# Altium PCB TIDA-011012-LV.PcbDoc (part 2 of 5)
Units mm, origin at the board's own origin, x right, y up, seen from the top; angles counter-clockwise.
Board outline 250 x 280 mm, 4 copper layers (Top Layer, Layer 1, Layer 2, Bottom Layer), stack 2.208 mm thick; 410 components, 230 nets, 1280 pads, 1868 vias.
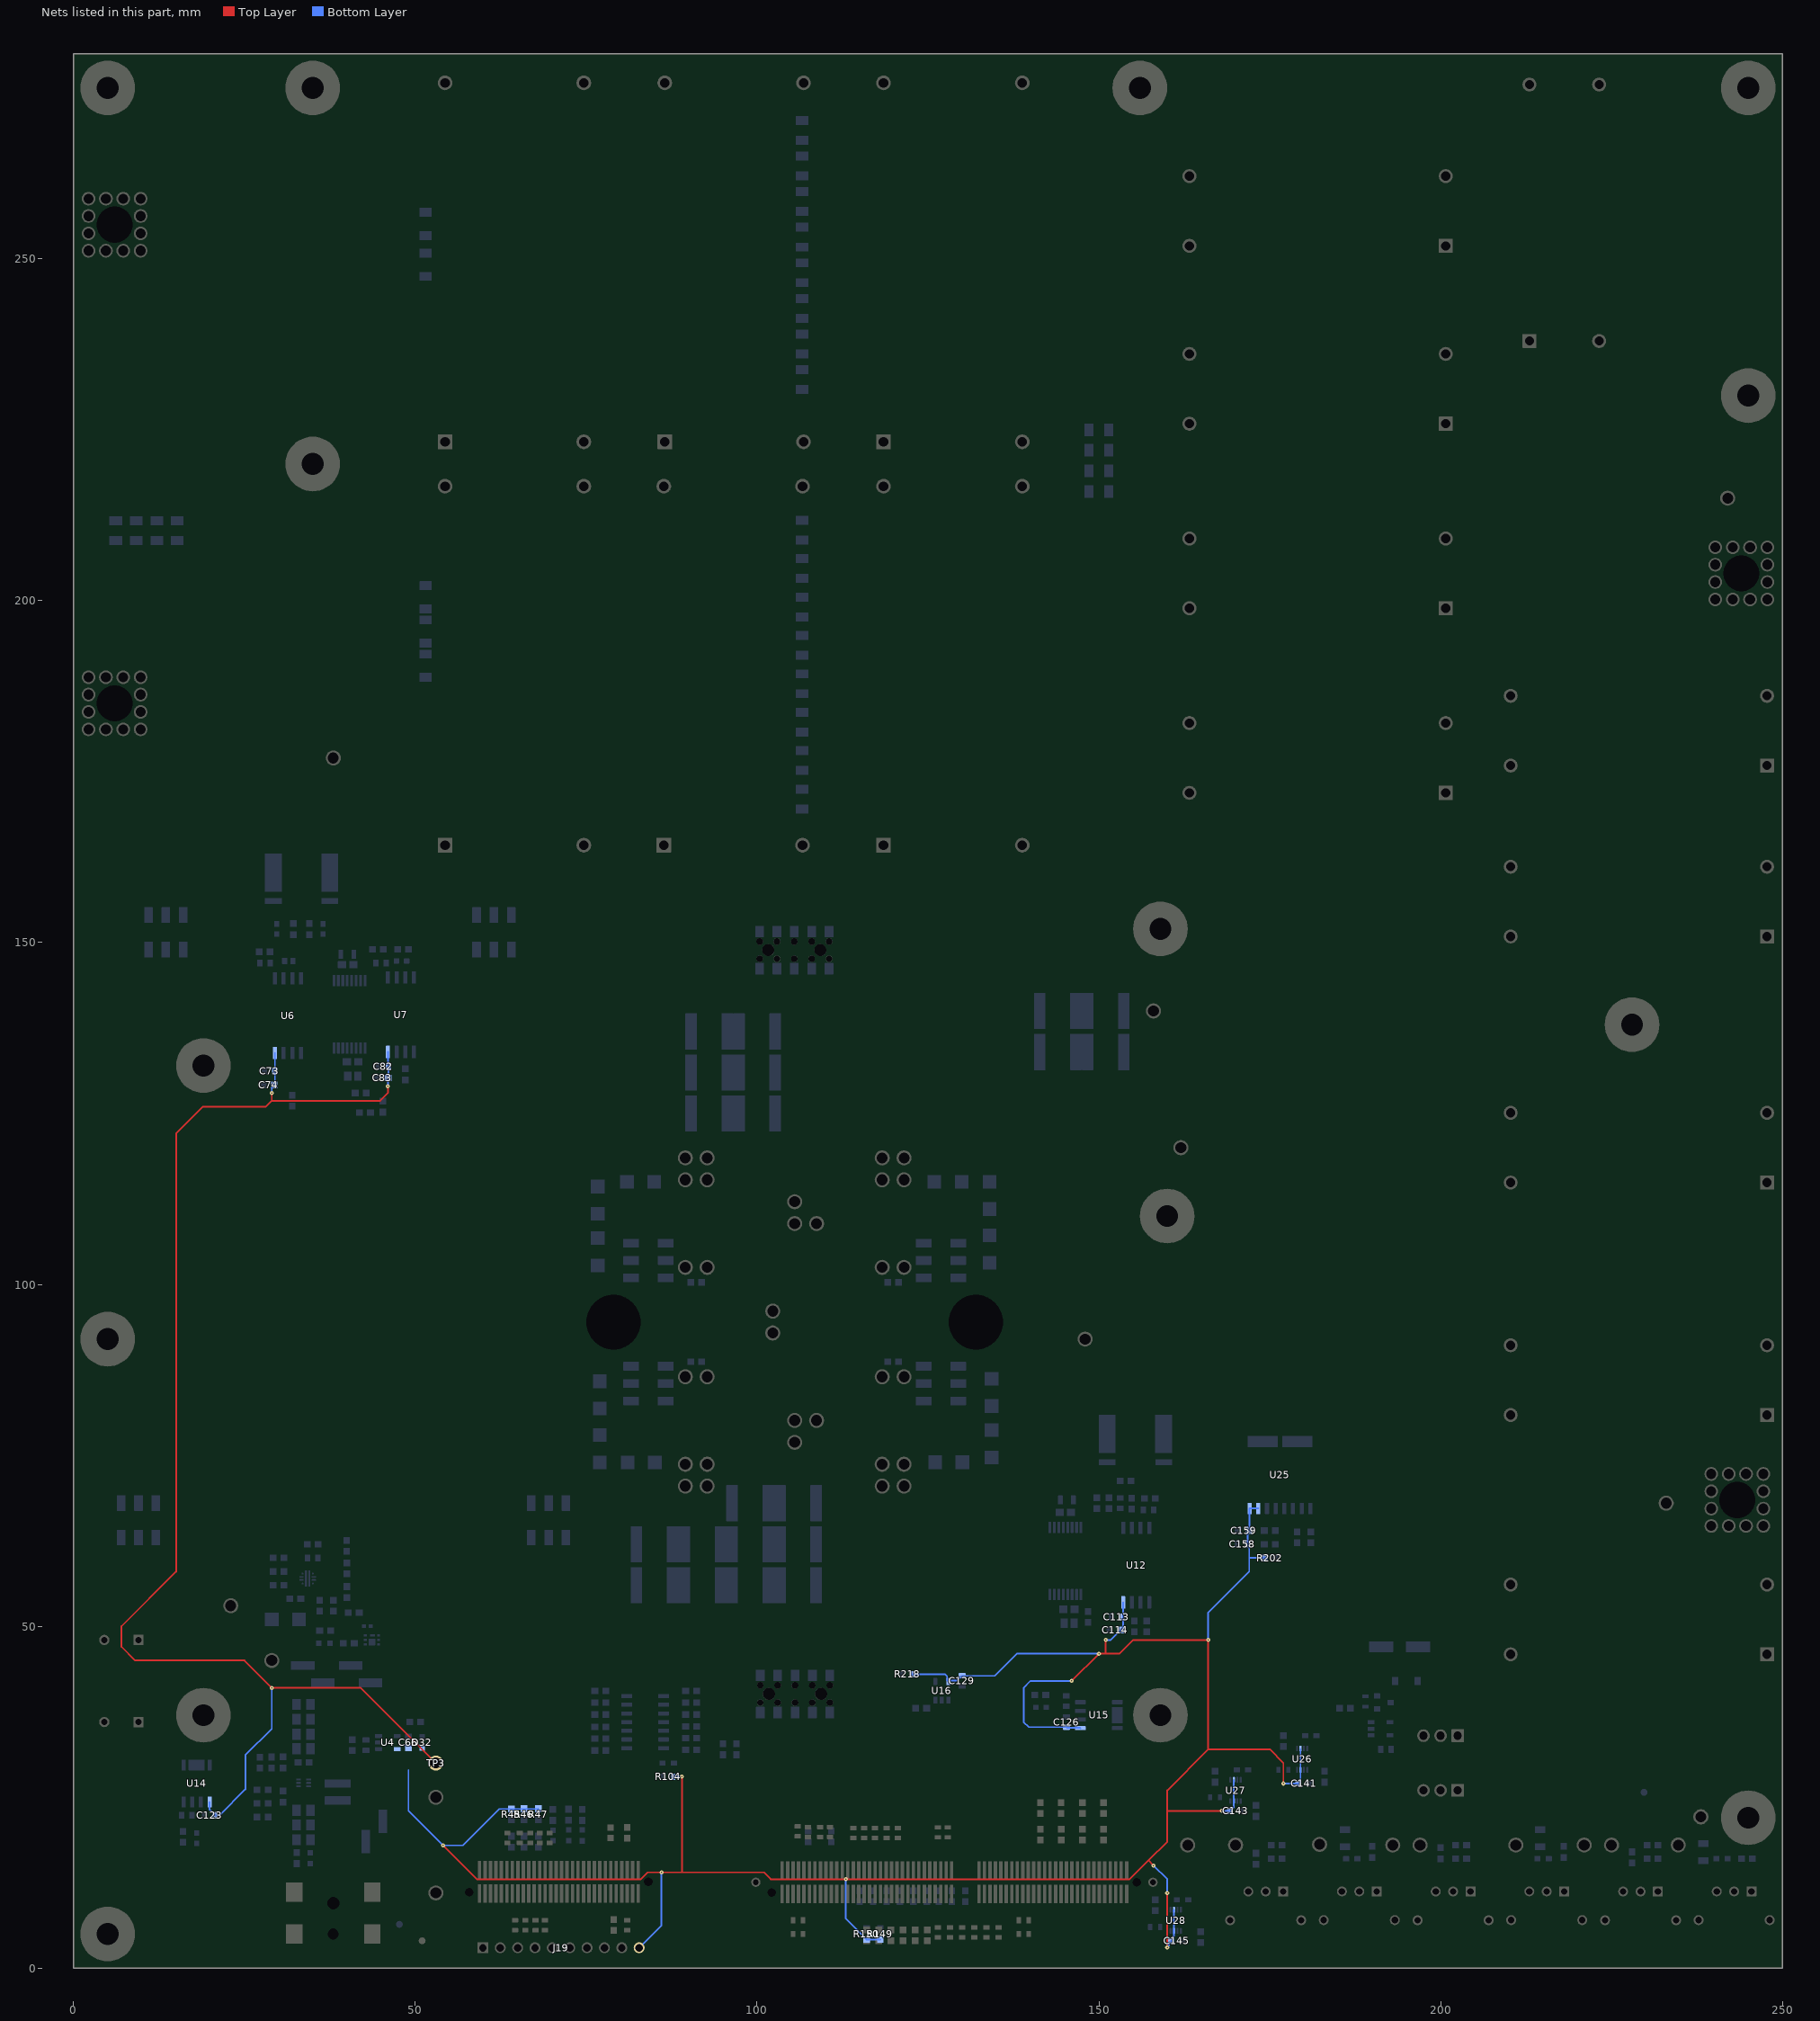
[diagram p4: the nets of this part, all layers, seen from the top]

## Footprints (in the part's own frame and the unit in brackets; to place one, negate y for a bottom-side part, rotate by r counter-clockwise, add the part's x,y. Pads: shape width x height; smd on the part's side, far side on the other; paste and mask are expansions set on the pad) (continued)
controlCARD-120HSEC [mm] "Pads are not numbered according to Samtec datasheet."
  rect 0.5x2.724 smd: 1(-23.357,-1.678) 2(-23.357,1.722) 3(-22.557,-1.678) 4(-22.557,1.722) 5(-21.757,-1.678) 6(-21.757,1.722) 7(-20.957,-1.678) 8(-20.957,1.722) 9(-20.157,-1.678) 10(-20.157,1.722) 11(-19.357,-1.678) 12(-19.357,1.722) 13(-18.557,-1.678) 14(-18.557,1.722) 15(-17.757,-1.678) 16(-17.757,1.722) 17(-16.957,-1.678) 18(-16.957,1.722) 19(-16.157,-1.678) 20(-16.157,1.722) 21(-15.357,-1.678) 22(-15.357,1.722) 23(-14.557,-1.678) 24(-14.557,1.722) 25(-13.757,-1.678) 26(-13.757,1.722) 27(-12.957,-1.678) 28(-12.957,1.722) 29(-12.157,-1.678) 30(-12.157,1.722) 31(-11.357,-1.678) 32(-11.357,1.722) 33(-10.557,-1.678) 34(-10.557,1.722) 35(-9.757,-1.678) 36(-9.757,1.722) 37(-8.957,-1.678) 38(-8.957,1.722) 39(-8.157,-1.678) 40(-8.157,1.722) 41(-7.357,-1.678) 42(-7.357,1.722) 43(-6.557,-1.678) 44(-6.557,1.722) 45(-5.757,-1.678) 46(-5.757,1.722) 47(-4.957,-1.678) 48(-4.957,1.722) 49(-4.157,-1.678) 50(-4.157,1.722) 51(-3.357,-1.678) 52(-3.357,1.722) 53(-2.557,-1.678) 54(-2.557,1.722) 55(-1.757,-1.678) 56(-1.757,1.722) 57(2.243,-1.678) 58(2.243,1.722) 59(3.043,-1.678) 60(3.043,1.722) 61(3.843,-1.678) 62(3.843,1.722) 63(4.643,-1.678) 64(4.643,1.722) 65(5.443,-1.678) 66(5.443,1.722) 67(6.243,-1.678) 68(6.243,1.722) 69(7.043,-1.678) 70(7.043,1.722) 71(7.843,-1.678) 72(7.843,1.722) 73(8.643,-1.678) 74(8.643,1.722) 75(9.443,-1.678) 76(9.443,1.722) 77(10.243,-1.678) 78(10.243,1.722) 79(11.043,-1.678) 80(11.043,1.722) 81(11.843,-1.678) 82(11.843,1.722) 83(12.643,-1.678) 84(12.643,1.722) 85(13.443,-1.678) 86(13.443,1.722) 87(14.243,-1.678) 88(14.243,1.722) 89(15.043,-1.678) 90(15.043,1.722) 91(15.843,-1.678) 92(15.843,1.722) 93(16.643,-1.678) 94(16.643,1.722) 95(17.443,-1.678) 96(17.443,1.722) 97(18.243,-1.678) 98(18.243,1.722) 99(19.043,-1.678) 100(19.043,1.722) 101(19.843,-1.678) 102(19.843,1.722) 103(20.643,-1.678) 104(20.643,1.722) 105(21.443,-1.678) 106(21.443,1.722) 107(22.243,-1.678) 108(22.243,1.722) 109(23.043,-1.678) 110(23.043,1.722) 111(23.843,-1.678) 112(23.843,1.722) 113(24.643,-1.678) 114(24.643,1.722) 115(25.443,-1.678) 116(25.443,1.722) 117(26.243,-1.678) 118(26.243,1.722) 119(27.043,-1.678) 120(27.043,1.722)
  round 0.025 hole 1.27 unplated mask+0.876: 181(-24.857,0.022) 182(28.543,1.522)
  round 1.348 hole 0.84: 185(-27.207,0.022) 186(30.893,0.022)
  silkscreen extent -32.11,-3.86 35.8,3.9, body extent -31.75,-3.47 35.3,3.53, height 12.35
controlCARD-180HSEC-60pinAddon [mm] "Pads are not numbered according to datasheet."
  round 0.025 hole 1.27 unplated mask+0.876: 61(-13.1,0) 62(13.1,1.5)
  rect 0.5x2.724 smd: 121(-11.6,-1.7) 122(-11.6,1.7) 123(-10.8,-1.7) 124(-10.8,1.7) 125(-10,-1.7) 126(-10,1.7) 127(-9.2,-1.7) 128(-9.2,1.7) 129(-8.4,-1.7) 130(-8.4,1.7) 131(-7.6,-1.7) 132(-7.6,1.7) 133(-6.8,-1.7) 134(-6.8,1.7) 135(-6,-1.7) 136(-6,1.7) 137(-5.2,-1.7) 138(-5.2,1.7) 139(-4.4,-1.7) 140(-4.4,1.7) 141(-3.6,-1.7) 142(-3.6,1.7) 143(-2.8,-1.7) 144(-2.8,1.7) 145(-2,-1.7) 146(-2,1.7) 147(-1.2,-1.7) 148(-1.2,1.7) 149(-0.4,-1.7) 150(-0.4,1.7) 151(0.4,-1.7) 152(0.4,1.7) 153(1.2,-1.7) 154(1.2,1.7) 155(2,-1.7) 156(2,1.7) 157(2.8,-1.7) 158(2.8,1.7) 159(3.6,-1.7) 160(3.6,1.7) 161(4.4,-1.7) 162(4.4,1.7) 163(5.2,-1.7) 164(5.2,1.7) 165(6,-1.7) 166(6,1.7) 167(6.8,-1.7) 168(6.8,1.7) 169(7.6,-1.7) 170(7.6,1.7) 171(8.4,-1.7) 172(8.4,1.7) 173(9.2,-1.7) 174(9.2,1.7) 175(10,-1.7) 176(10,1.7) 177(10.8,-1.7) 178(10.8,1.7) 179(11.6,-1.7) 180(11.6,1.7)
  silkscreen extent -14.68,-3.88 14.68,3.88, body extent -14.3,-3.5 14.3,3.5, height 7.95
CUI_PJ-002AH-SMT [mm] "CUI"
  rect 2.8x2.4 smd: 1(-3.05,5.7) 1A(3.05,5.7) 2(-3.05,-5.7) 3(3.05,-5.7)
  round 1 hole 1.6 unplated: MH1(-3.05,0)
  round 1.524 hole 1.8 unplated: MH2(1.45,0)
  silkscreen extent -8.05,-4.5 6.75,5.45, body extent -8.05,-6.3 6.75,6.3, height 11.2
D0014A-MFG [mm]
  rrect17% 1.55x0.6 smd paste-1000 mask+0: 1(-2.7,3.81) 2(-2.7,2.54) 3(-2.7,1.27) 4(-2.7,0) 5(-2.7,-1.27) 6(-2.7,-2.54) 7(-2.7,-3.81) 8(2.7,-3.81) 9(2.7,-2.54) 10(2.7,-1.27) 11(2.7,0) 12(2.7,1.27) 13(2.7,2.54) 14(2.7,3.81)
  silkscreen extent -4.15,-4.38 1.55,4.38, body extent -3,-4.33 3,4.33, height 1.75
DBV0005A_N [mm] "SOT23, 5-Leads, Body 2.9x1.6mm, Pitch 0.95mm, Lead Span 2.8mm, IPC Medium Density"
  rrect17% 1x0.6 smd: 1(-1.375,0.95) 2(-1.375,0) 3(-1.375,-0.95) 4(1.375,-0.95) 5(1.375,0.95)
  silkscreen extent -0.25,-1.55 0.25,1.55, body extent -1.42,-1.46 1.42,1.46, height 1.09
DCU0008A-MFG [mm]
  rrect33% 0.8x0.3 smd paste-1000 mask+0: 1(-1.55,0.75) 2(-1.55,0.25) 3(-1.55,-0.25) 4(-1.55,-0.75) 5(1.55,-0.75) 6(1.55,-0.25) 7(1.55,0.25) 8(1.55,0.75)
  silkscreen extent -2.62,-1.05 0.78,1.05, body extent -1.55,-1 1.55,1, height 0.9
DFQ0007A-MFG [mm]
  rrect17% 1.55x0.6 smd paste+0 mask+0: 1(-2.7,1.905) 2(-2.7,0.635) 3(-2.7,-0.635) 4(-2.7,-1.905) 5(2.7,-1.905) 7(2.7,1.905)
  rrect6% 1.55x2.36 smd paste+0 mask+0: 6(2.7,0)
  silkscreen extent -4.14,-2.5 1.55,2.5, body extent -3.01,-2.45 3.01,2.45, height 1.75
DHA0016A-MFG [mm]
  rrect24% 1.65x0.41 smd paste+0 mask+0: 1(-4.925,2.275) 2(-4.925,1.625) 3(-4.925,0.975) 4(-4.925,0.325) 5(-4.925,-0.325) 6(-4.925,-0.975) 7(-4.925,-1.625) 8(-4.925,-2.275) 9(4.925,-2.275) 10(4.925,-1.625) 11(4.925,-0.975) 12(4.925,-0.325) 13(4.925,0.325) 14(4.925,0.975) 15(4.925,1.625) 16(4.925,2.275)
  silkscreen extent -6.42,-2.98 3.5,2.98, body extent -5.15,-2.93 5.15,2.93, height 2.6
DQK0006C [mm] "WSON"
  rrect12% 0.9x0.86 on Bottom Paste: 0(0,0.325)
  rrect34% 0.7x0.29 on Bottom Paste: 0(0.095,-0.65)
  rrect33% 0.45x0.3 smd: 1(-0.975,0.65) 2(-0.975,0) 3(-0.975,-0.65) 4(0.975,-0.65) 5(0.975,0) 6(0.975,0.65)
  rrect33% 0.75x0.3 smd paste-0.15: 7(0.095,-0.65)
  rrect11% 1x0.95 smd paste-0.5: 8(0,0.325)
  silkscreen extent -1.15,-1.15 1.15,1.15, body extent -1,-1 1,1, height 0.82
DRL0006A-MFG [mm]
  rrect33% 0.67x0.3 smd paste+0 mask+0: 1(-0.74,0.5) 2(-0.74,0) 3(-0.74,-0.5) 4(0.74,-0.5) 5(0.74,0) 6(0.74,0.5)
  silkscreen extent -1.75,-1.05 0.65,1.05, body extent -0.8,-0.8 0.8,0.8, height 0.6
DVG0010A-MFG [mm]
  rrect6% 1.65x4.41 smd paste+0 mask+0: 1(-4.875,2.54) 2(-4.875,-2.54)
  rrect17% 1.65x0.6 smd paste+0 mask+0: 3(4.875,-4.445) 4(4.875,-3.175) 5(4.875,-1.905) 6(4.875,-0.635) 7(4.875,0.635) 8(4.875,1.905) 9(4.875,3.175) 10(4.875,4.445)
  silkscreen extent -6.37,-5.25 3.67,5.25, body extent -5.15,-5.15 5.15,5.15, height 2.65
DWV0008A [mm] "SOIC, 8-Leads, Body 5.95x7.6mm (max), Pitch 1.27mm"
  rrect17% 1.8x0.6 smd: 1(-5.45,1.905) 2(-5.45,0.635) 3(-5.45,-0.635) 4(-5.45,-1.905) 5(5.45,-1.905) 6(5.45,-0.635) 7(5.45,0.635) 8(5.45,1.905)
  silkscreen extent -6.25,-2.95 2.98,2.95, body extent -5.77,-2.92 5.77,2.93, height 2.67
DWV0008A-MFG [mm] "Recommended Land Pattern"
  rrect17% 1.8x0.6 smd paste+0 mask+0: 1(-5.45,1.905) 2(-5.45,0.635) 3(-5.45,-0.635) 4(-5.45,-1.905) 5(5.45,-1.905) 6(5.45,-0.635) 7(5.45,0.635) 8(5.45,1.905)
  silkscreen extent -7.1,-2.98 3.8,2.98, body extent -5.75,-2.93 5.75,2.93, height 2.8
FCC_disclaimer [mm]
Fiducial10-20 [mm]
  round 1 smd mask+0.5: 1(0,0)
  Top Layer keep-out circle w1.178: c0,0 r0.5
FP-0603ZC102KAT2A_0603-MFG [mm]
  rrect13% 0.8x0.75 smd paste+0 mask+0: 1(-0.75,0) 2(0.75,0)
  silkscreen extent -0.87,-0.77 0.87,0.77, body extent -0.8,-0.41 0.8,0.41, height 0.9
FP-06031C101JAT2A_0603-MFG [mm]
  rrect13% 0.8x0.75 smd paste+0 mask+0: 1(-0.75,0) 2(0.75,0)
  silkscreen extent -0.87,-0.77 0.87,0.77, body extent -0.8,-0.41 0.8,0.41, height 0.9
FP-0022111031_HDR3-MFG [mm]
  rrect5% 1.85x1.85 hole 1.2 paste-2539.97 mask+0: 1(2.5,0.3)
  round 1.85 hole 1.2 paste-2539.97 mask+0: 2(0,0.3) 3(-2.5,0.3)
  silkscreen extent -4.1,-3.1 4.7,3.1, body extent -3.5,-2.9 3.5,2.9, height 12.1
FP-74439324047_SMD2-MFG [mm] "Recommended Land Pattern"
  rrect8% 1.2x3.8 smd paste+0 mask+0: 1(-1.225,0) 2(1.225,0)
  silkscreen extent -2.87,-2.25 0.25,2.25, body extent -2.15,-2.15 2.15,2.15, height 3.2
FP-C4AQJBW5550M3MJ_PTH_CAP_57MM5_30MM0-MFG [mm] "Recommended Land Pattern"
  round 2.15 hole 1.4 paste-2539.97 mask+0: 1(-26.25,-10.15) 2(26.25,-10.15) 2(26.25,10.15)
  rrect5% 2.15x2.15 hole 1.4 paste-2539.97 mask+0: 1(-26.25,10.15)
  silkscreen extent -29.15,-15.25 29.15,15.25, body extent -28.75,-15 28.75,15, height 45.3
FP-C4ASMBW4200A3HJ_RADIAL-MFG [mm] "Recommended Land Pattern"
  round 2.05 hole 1.35 paste-2539.97 mask+0: 1(-18.75,-5.1) 2(18.75,-5.1) 2(18.75,5.1)
  rrect5% 2.05x2.05 hole 1.35 paste-2539.97 mask+0: 1(-18.75,5.1)
  silkscreen extent -20.75,-12 20.75,12, body extent -20.75,-12 20.75,12, height 44
FP-C0603C103J3GAC7867_0603-MFG [mm]
  rrect13% 0.75x0.9 smd paste+0 mask+0: 1(-0.6,0) 2(0.6,0)
  silkscreen extent -0.87,-0.82 0.87,0.82, body extent -0.8,-0.4 0.8,0.4, height 0.87
FP-C0603C153K5RACTU_0603-IPC_A [mil]
  rrect9% 47.5x41.66 smd paste+0 mask+0: 1(-32.51,0) 2(32.51,0)
  body extent -31,-16 31,16, height 34
FP-C2220X103KHRAC7800_2220-MFG [mm] "Recommended Land Pattern"
  rrect6% 1.7x5.3 smd paste+0 mask+0: 1(-2.65,0) 2(2.65,0)
  silkscreen extent -1.43,-2.7 1.43,2.7, body extent -2.95,-2.5 2.95,2.5, height 2.2
FP-CHV1206-FX-1504ELF_1206-MFG [mm]
  rrect8% 1.3x1.8 smd paste+0 mask+0: 1(-1.7,0) 2(1.7,0)
  silkscreen extent -0.67,-0.85 0.67,0.85, body extent -1.55,-0.8 1.55,0.8, height 0.65
FP-CL10B104KA8VPJC_0603-MFG [mm]
  rrect13% 0.79x1 smd paste+0 mask+0: 1(-0.755,0) 2(0.755,0)
  silkscreen extent -0.9,-0.87 0.9,0.87, body extent -0.8,-0.4 0.8,0.4, height 0.9
FP-CL10B105KA8VPJC_0603-MFG [mm]
  rrect13% 0.79x1 smd paste+0 mask+0: 1(-0.755,0) 2(0.755,0)
  silkscreen extent -0.9,-0.87 0.9,0.87, body extent -0.8,-0.4 0.8,0.4, height 0.9
FP-CRCW060310K0JNEBC_0603-MFG [mm]
  rrect20% 0.5x0.9 smd paste+0 mask+0: 1(-0.75,0) 2(0.75,0)
  silkscreen extent -0.13,-0.45 0.13,0.45, body extent -0.77,-0.4 0.77,0.4, height 0.5
FP-DMN3042L-13_SOT23-MFG [mm]
  rrect13% 0.9x0.8 smd paste+0 mask+0: 1(-1,0.95) 2(-1,-0.95) 3(1,0)
  silkscreen extent -0.7,-1.5 0.7,1.5, body extent -1.2,-1.45 1.2,1.45, height 1.1
FP-ERJ-H3G0R00V_0603-IPC_B [mm]
  rrect10% 0.957x0.962 smd paste+0 mask+0: 1(-0.751,0) 2(0.751,0)
  silkscreen extent -1.23,-0.88 1.23,0.88, body extent -0.8,-0.4 0.8,0.4, height 0.55
FP-ERJ-H3G0R00V_0603-MFG [mm]
  rrect15% 0.65x0.9 smd paste+0 mask+0: 1(-0.725,0) 2(0.725,0)
  silkscreen extent 0,-0.48 0,0.48, body extent -0.8,-0.4 0.8,0.4, height 0.55
FP-G4H22MT33GB4_SiCPAK-G+_MODIFIED-MFG [mm] "Recommended Land Pattern Modified"
  round 2.2 hole 1.6 paste-2539.97 mask+0: AC1(20.8,12.8) AC1(20.8,16) AC1(24,12.8) AC1(24,16) AC2(-24,12.8) AC2(-24,16) AC2(-20.8,12.8) AC2(-20.8,16) DC1+(20.8,-16) DC1+(20.8,-12.8) DC1+(24,-16) DC1+(24,-12.8) DC1-(14.4,0) DC1-(14.4,3.2) DC1-(17.6,0) DC2+(-24,-16) DC2+(-24,-12.8) DC2+(-20.8,-16) DC2+(-20.8,-12.8) DC2-(-17.6,0) DC2-(-14.4,0) DC2-(-14.4,3.2) G1(8,-12.8) G2(8,12.8) G3(-8,-12.8) G4(-8,12.8) KS1(8,-16) KS2(8,16) KS3(-8,-16) KS4(-8,16) T1(-1.6,-3.2) T2(1.6,-3.2)
  round 4.6 hole 8 unplated paste-2539.97 mask+0: ""(0,26.5) ""(0,-26.5)
  silkscreen extent -28.45,-24.1 29.12,24.1, body extent -28.35,-32.49 28.35,32.51, height 12.9
FP-GMC10X7R104K25NT_0603-MFG [mil]
  rrect13% 35x30 smd paste+0 mask+0: 1(-32.5,0) 2(32.5,0)
  silkscreen extent -35,-31 35,31, body extent -31,-16 31,16, height 39
FP-GRT21BD71A226ME13L_0805-MFG [mm]
  rrect14% 0.7x1.3 smd paste+0 mask+0: 1(-0.95,0) 2(0.95,0)
  silkscreen extent -0.23,-0.72 0.23,0.72, body extent -1,-0.63 1,0.63, height 1.45
FP-HLE-105-02-G-DV-BE-A_CONN_RCPT_10-MFG [mm] "Recommended Land Pattern"
  rrect8% 1.27x1.68 smd paste+0 mask+0: 1(5.08,-2.72) 2(5.08,2.72) 3(2.54,-2.72) 4(2.54,2.72) 5(0,-2.72) 6(0,2.72) 7(-2.54,-2.72) 8(-2.54,2.72) 9(-5.08,-2.72) 10(-5.08,2.72)
  round 0.97 hole 0.97 unplated paste-2539.97 mask+0: ""(-5.08,-1.27) ""(-5.08,1.27) ""(-2.54,-1.27) ""(-2.54,1.27) ""(0,-1.27) ""(0,1.27) ""(2.54,-1.27) ""(2.54,1.27) ""(5.08,-1.27) ""(5.08,1.27)
  round 1.78 hole 1.78 unplated paste-2539.97 mask+0: ""(-3.81,0) ""(3.81,0)
  silkscreen extent -6.45,-3.43 6.45,2.61, body extent -6.35,-3.29 6.35,3.29, height 3.79
FP-LSL29K-G1H2-1-Z_0603-0 [mm]
  rrect13% 0.8x0.8 smd paste-1000 mask+0: 1(-0.75,0) 2(0.75,0)
  silkscreen extent -1.77,-0.77 0.7,0.77, body extent -0.85,-0.4 0.85,0.4, height 0.67
FP-MA0805XR106K160_0805-IPC_C [mm]
  rrect9% 1.055x1.356 smd paste+0 mask+0: 1(-0.726,0) 2(0.726,0)
  silkscreen extent -1.25,-1.12 1.25,1.12, body extent -1,-0.63 1,0.63, height 1.45
FP-TORX1350A(F)_OPTIC_RECIEVER_13MM0_13MM5-MFG [mm]
  rrect7% 1.45x1.45 hole 0.95 paste-2539.97 mask+0: 1(-2.54,-4.05)
  round 1.45 hole 0.95 paste-2539.97 mask+0: 2(0,-4.05) 3(2.54,-4.05) 4(5.2,0.15) 5(-5.2,0.15)
  silkscreen extent -6.65,-7.5 6.65,6.9, body extent -6.5,-6.75 6.5,6.75, height 8.8
FP-TOTX1350(F)_REC_OPT_PTH-MFG [mm]
  rrect7% 1.45x1.45 hole 0.95 paste-2539.97 mask+0: 1(-2.54,-4.05)
  round 1.45 hole 0.95 paste-2539.97 mask+0: 2(0,-4.05) 3(2.54,-4.05) 4(5.2,0.15) 5(-5.2,0.15)
  silkscreen extent -6.65,-7.52 6.65,6.9, body extent -6.5,-6.75 6.5,6.75, height 8.8
IEC_HighVoltage_Medium [mm]
  silkscreen extent -5.51,-4.46 5.51,5.09
IEC_HotSurface_Medium [mm]
  silkscreen extent -5.51,-4.76 5.51,4.78
Keystone5010 [mil] "Keystone Multipurpose loops"
  round 87 hole 63: 1(0,0)
  silkscreen extent -70,-70 70,70, body extent -63,-63 62,62, height 319
Keystone5011 [mil] "Keystone Multipurpose loops"
  round 87 hole 63: 1(0,0)
  silkscreen extent -70,-70 70,70, body extent -63,-63 62,62, height 319
Keystone5122 [mil] "Keystone Compact loops"
  round 87 hole 63: 1(0,0)
  silkscreen extent -70,-70 70,70, body extent -63,-63 62,62, height 225
Label_650x200 [mil] "Thermal Transfer Label"
  round 1 on Mech14: 0(0,0)
  silkscreen extent -325,-100 325,100, body extent -325,-100 325,100, height 1
NLCV25 [mm] "TDK"
  rect 1x1.5 smd: 1(-1.25,0) 2(1.25,0)
  body extent -1.35,-1.05 1.35,1.05, height 1.9
"NY PMS 440 0025 PH" [mm] "4-40 nylon screw and mounting hole"
  round 8 hole 3.2: 1(0,0)
  body extent -3.31,-3.3 3.3,3.3, height 2.69
RPW0010A-MFG [mm]
  round 0.27 smd paste-1000 mask+0: 1(-0.75,0.7) 10(0.75,0.7)
  rrect40% 0.6x0.25 smd paste+0 mask+0: 2(-0.9,0.225) 3(-0.9,-0.225) 8(0.9,-0.225) 9(0.9,0.225)
  round 0.255 smd paste-1000 mask+0: 4(-0.75,-0.75) 7(0.75,-0.75)
  rrect33% 0.3x2.4 smd paste-1000 mask+0: 5(-0.25,0) 6(0.25,0)
  Top Layer region: 0.85,0.85 0.85,1.15 0.846,1.169 0.835,1.185 0.819,1.196 0.8,1.2 0.8,1.2 0.65,1.2 0.631,1.196 0.615,1.185 0.604,1.169 0.6,1.15 0.6,1.15 0.6,0.6 0.604,0.581 0.615,0.565 0.631,0.554 0.65,0.55 0.65,0.55 1.15,0.55 1.169,0.554 1.185,0.565 1.196,0.581 1.2,0.6 1.2,0.6 1.2,0.8 1.196,0.819 1.185,0.835 1.169,0.846 1.15,0.85 1.15,0.85
  Top Layer region: 0.85,-0.85 0.85,-1.15 0.846,-1.169 0.835,-1.185 0.819,-1.196 0.8,-1.2 0.8,-1.2 0.65,-1.2 0.631,-1.196 0.615,-1.185 0.604,-1.169 0.6,-1.15 0.6,-1.15 0.6,-0.6 0.604,-0.581 0.615,-0.565 0.631,-0.554 0.65,-0.55 0.65,-0.55 1.15,-0.55 1.169,-0.554 1.185,-0.565 1.196,-0.581 1.2,-0.6 1.2,-0.6 1.2,-0.8 1.196,-0.819 1.185,-0.835 1.169,-0.846 1.15,-0.85 1.15,-0.85
  Top Layer region: -0.85,-0.85 -0.85,-1.15 -0.846,-1.169 -0.835,-1.185 -0.819,-1.196 -0.8,-1.2 -0.8,-1.2 -0.65,-1.2 -0.631,-1.196 -0.615,-1.185 -0.604,-1.169 -0.6,-1.15 -0.6,-1.15 -0.6,-0.6 -0.604,-0.581 -0.615,-0.565 -0.631,-0.554 -0.65,-0.55 -0.65,-0.55 -1.15,-0.55 -1.169,-0.554 -1.185,-0.565 -1.196,-0.581 -1.2,-0.6 -1.2,-0.6 -1.2,-0.8 -1.196,-0.819 -1.185,-0.835 -1.169,-0.846 -1.15,-0.85 -1.15,-0.85
  Top Layer region: -0.85,0.85 -0.85,1.15 -0.843,1.175 -0.825,1.193 -0.8,1.2 -0.8,1.2 -0.65,1.2 -0.631,1.196 -0.615,1.185 -0.604,1.169 -0.6,1.15 -0.6,1.15 -0.6,0.6 -0.604,0.581 -0.615,0.565 -0.631,0.554 -0.65,0.55 -0.65,0.55 -1.15,0.55 -1.169,0.554 -1.185,0.565 -1.196,0.581 -1.2,0.6 -1.2,0.6 -1.2,0.8 -1.193,0.825 -1.175,0.843 -1.15,0.85 -1.15,0.85
  silkscreen extent -1.88,-1.58 1.05,1.58, body extent -1,-1 1,1, height 1
Samtec_HLE-103-02-x-DV [mm] "Receptacle, 2.54mm, 3x2, SMT"
  rrect8% 1.27x2.29 smd: 1(-2.54,2.525) 2(-2.54,-2.525) 3(0,2.525) 4(0,-2.525) 5(2.54,2.525) 6(2.54,-2.525)
  body extent -3.81,-3.29 3.81,3.29, height 3.66
Samtec_TSM-102-01-T-SV-P-TR [mil] "SMD, 2-Leads, Body 200x100mil"
  rect 50x135 smd: 1(-50,57.5) 2(50,-57.5)
  silkscreen extent -100,-50 100,92, body extent -100,-97 100,96, height 380
SMA [mm] "Molded Diode, 2-Leads, Body 4.3x2.6mm, IPC Medium Density, based on OnSemi component dimensions and land pattern"
  rect 2x2 smd: 1(-2,0) 2(2,0)
  silkscreen extent -3.66,-1.57 2.79,1.57, body extent -2.6,-1.3 2.6,1.3, height 2.42
SOD-123 [mm] "On Semi recommended land pattern"
  rect 0.915x1.22 smd: 1(-1.637,0) 2(1.637,0)
  silkscreen extent -2.74,-1.17 2.03,1.17, body extent -1.93,-0.9 1.93,0.9, height 1.35
UWT_630x770 [mm] "SMD, 2-Leads, Dia 6.3mm"
  rrect6% 3.5x1.6 smd: 1(-2.7,0) 2(2.7,0)
  body extent -3.5,-3.3 3.5,3.3, height 8
WEEE_Minimum [mm] "WEEElie bin"
  silkscreen extent -2.42,-4.38 2.52,2.65
WL-SMCW_GREEN [mm] "WURTH"
  rect 0.8x0.8 smd: 1(-0.8,0) 2(0.8,0)
  silkscreen extent -1.9,-0.8 1.2,0.8, body extent -0.85,-0.45 0.85,0.45, height 0.8
WSL4026_0p5milli [mm] "VISHAY"
  rect 2.44x5.6 smd: 1(-4.115,-0.89) 2(4.115,-0.89)
  rect 2.44x0.89 smd: 3(-4.115,3.245) 4(4.135,3.245)
  silkscreen extent -5.25,-3.49 5.1,3.51, body extent -5.05,-3.3 5.05,3.3, height 2.96
Wurth_7461086 [mm] "Bush, M4, TH"
  round 2 hole 1.475: 1(-3.81,-3.81) 1(-3.81,-1.27) 1(-3.81,1.27) 1(-3.81,3.81) 1(-1.27,-3.81) 1(-1.27,3.81) 1(1.27,-3.81) 1(1.27,3.81) 1(3.81,-3.81) 1(3.81,-1.27) 1(3.81,1.27) 1(3.81,3.81)
  round 0 hole 5.3 unplated: ""(0,0)
  body extent -4.5,-4.5 4.5,4.5, height 6.1
Wurth_61301011121 [mm] "Header, 2.54mm, 10x1, TH"
  rect 1.6x1.6 hole 1.1: 1(-11.43,0)
  round 1.6 hole 1.1: 2(-8.89,0) 3(-6.35,0) 4(-3.81,0) 5(-1.27,0) 6(1.27,0) 7(3.81,0) 8(6.35,0) 9(8.89,0) 10(11.43,0)
  silkscreen extent -12.7,-1.27 12.7,1.6, body extent -12.7,-1.27 12.7,1.27, height 8.54

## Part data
C1 C2 C173 C174 C175 C176 C177 C178 C179 C180: library part CMP-0128991-1, "2 µF Film Capacitor 500V 850V Polypropylene (PP), Metallized Radial - 4 Leads", Digikey Part Number=399-13083-ND, Manufacturer=KEMET, Mouser Part Number=80-C4ASMBW4200A3HJ, Operating Temperature Range="-40°C to +85°C", Tolerance_%=5%, ValueDisplayed=2uF
C7 C8 C9 C19 C20 C21: library part CMP-0128990-1, "55 µF Film Capacitor 700V Polypropylene (PP), Metallized Radial - 4 Leads", Digikey Part Number=399-C4AQJBW5550M3MJ-ND, Manufacturer=KEMET, Mouser Part Number=80-C4AQJBW5550M3MJ, Operating Temperature Range="-55°C to +105°C", Tolerance_%=5%, ValueDisplayed=55uF
C10 C22 C73 C75 C82 C84 C111 C113 C117 C123 C125 C126 C128 C129 C146: library part CMP-0121051-1, "Automotive CAP, 100㎋, 25V, ±10%, X7R, 0603, 5mm Bending", Manufacturer=Samsung, Mouser Part Number=187-CL10B104KA8VPJC, Operating Temperature Range="-55°C to +125°C", TempCo=15%, Temperature Characteristic=X7R, Tolerance_%=10%, ValueDisplayed=100nF
C11 C12 C13 C23 C24 C25 C65 C71 C163 C164 C190 C191 C192 C193 C194 C195 C196 C197 C198 C199: library part CMP-0128868-1, "10000 pF ±10% 3000V (3kV) Ceramic Capacitor X7R 2220 (5750 Metric)", Digikey Part Number=399-C2220X103KHRACTUCT-ND, Manufacturer=KEMET, Mouser Part Number=80-C2220X103KHR, Operating Temperature Range="-55°C to +125°C", TempCo=15%, Temperature Characteristic=X7R, Tolerance_%=10%, ValueDisplayed=0.01uF
C27 C29 C30 C33 C34 C35 C40 C41 C43 C46 C49 C50 C51 C52 C53 C81: library part CMP-0006982-4, "CAP, CERM, 220 pF, 50 V, +/- 10%, X7R, 0603", Cap_Case=0603, Manufacturer=Kemet, Supplier Part Number 1=399-5342-1-ND, TempCo=X7R, Tolerance_%=10%, Value1=Unknown, Value2=50V, ValueDisplayed=220pF
C45 C135 C137 C138 C140 C141 C142 C143 C144 C145: library part CMP-0094950-1, "0.1 µF ±10% 25V Ceramic Capacitor X7R 0603 (1608 Metric)", Digikey Part Number=2571-GMC10X7R104K25NTTR-ND, Manufacturer="CAL-CHIP ELECTRONICS", Operating Temperature Range="-55°C to +125°C", TempCo=30ppm/°C, Temperature Characteristic=X7R, Tolerance_%=10%, ValueDisplayed=0.1uF
C55 C56: library part CMP-0010289-1, "CAP, AL, 1000 uF, 16 V, +/- 20%, TH", Cap_Case=10x16, Manufacturer=Rubycon, Supplier Part Number 1=1189-1151-ND, Tolerance_%=20%, Value1=Unknown, Value2=16V, ValueDisplayed=1000uF
C57 C59: library part CMP-0007052-4, "CAP, CERM, 1 uF, 35 V, +/- 10%, X7R, 0603", Cap_Case=0603, Manufacturer=TDK, Supplier Part Number 1=445-7414-1-ND, TempCo=X7R, Tolerance_%=10%, Value1=Unknown, Value2=35V, ValueDisplayed=1uF
C58 C171: library part CMP-0006752-5, "CAP, CERM, 0.1 uF, 25 V, +/- 5%, X7R, 0603", Cap_Case=0603, Manufacturer=AVX, Supplier Part Number 1=478-3713-1-ND, TempCo=X7R, Tolerance_%=5%, Value1="0.05 ohm", Value2=25V, ValueDisplayed=0.1uF
C60: library part CMP-0007477-4, "CAP, CERM, 2700 pF, 100 V, +/- 10%, X7R, 0603", Cap_Case=0603, Manufacturer=MuRata, Supplier Part Number 1=490-1480-1-ND, TempCo=X7R, Tolerance_%=10%, Value1=Unknown, Value2=100V, ValueDisplayed=2700pF
C61: library part CMP-0006985-4, "CAP, CERM, 3300 pF, 50 V, +/- 10%, X7R, 0603", Cap_Case=0603, Manufacturer=Kemet, Supplier Part Number 1=399-5339-1-ND, TempCo=X7R, Tolerance_%=10%, Value1=Unknown, Value2=50V, ValueDisplayed=3300pF
C62: library part CMP-0006659-2, "CAP, CERM, 0.1 uF, 25 V, +/- 10%, X7R, 0402", Cap_Case=0402, Manufacturer=MuRata, Supplier Part Number 1=490-10698-1-ND, TempCo=X7R, Tolerance_%=10%, Value1=Unknown, Value2=25V, ValueDisplayed=0.1uF
C63: library part CMP-0007255-4, "CAP, CERM, 22 pF, 100 V, +/- 5%, C0G/NP0, 0603", Cap_Case=0603, Manufacturer=MuRata, Supplier Part Number 1=490-1335-1-ND, TempCo=C0G/NP0, Tolerance_%=5%, Value1=Unknown, Value2=100V, ValueDisplayed=22pF
C64 C66: library part CMP-0007121-4, "CAP, CERM, 2.2 uF, 16 V, +/- 10%, X7R, 0603", Cap_Case=0603, Manufacturer="Taiyo Yuden", Supplier Part Number 1=EMK107BB7225KA-T-ND, TempCo=X7R, Tolerance_%=10%, Value1=Unknown, Value2=16V, ValueDisplayed=2.2uF
C67 C68 C69: library part CMP-0008377-2, "CAP, CERM, 22 uF, 10 V, +/- 20%, X7R, 0805", Cap_Case=0805, Manufacturer=MuRata, Supplier Part Number 1=81-GRM21BZ71A226ME5L, TempCo=X7R, Tolerance_%=20%, Value1=Unknown, Value2=10V, ValueDisplayed=22uF
C70 C72 C169 C170: library part CMP-0085283-1, "CAP, CERM, 10 µF, 16 V,+/- 10%, X7R, 0805", Cap_Case=0805, Manufacturer="Taiyo Yuden", TempCo=X7R, Tolerance_%=10%, Value2=16V, ValueDisplayed=10µF
C74 C76 C83 C85 C112 C114: library part CMP-0079605-1, "CAP, CERM, 2.2 µF, 16 V,+/- 10%, X7R, 0603", Cap_Case=0603, Manufacturer="Yageo America", Supplier Part Number 1=311-3490-1-ND, TempCo=X7R, Tolerance_%=10%, Value2=16V, ValueDisplayed=2.2µF
C77: library part CMP-0095473-1, "10000 pF ±5% 25V Ceramic Capacitor C0G, NP0 0603 (1608 Metric)", Digikey Part Number=399-C0603C103J3GAC7867CT-ND, Manufacturer=KEMET, Mouser Part Number=80-C0603C103J3G, Operating Temperature Range="-55°C to +125°C", TempCo=30ppm/°C, Temperature Characteristic=C0G, Tolerance_%=5%, ValueDisplayed=10000pF
C78 C87 C116 C147 C148 C149 C150 C151 C152 C153 C154 C155: library part CMP-0006811-4, "CAP, CERM, 10 pF, 10 V, +/- 10%, X7R, 0603", Cap_Case=0603, Manufacturer=AVX, Supplier Part Number 1=0603ZC100KAT2A-ND, TempCo=X7R, Tolerance_%=10%, Value1=Unknown, Value2=10V, ValueDisplayed=10pF
C79 C80: library part CMP-0120686-1, "1000 pF ±10% 10V Ceramic Capacitor X7R 0603 (1608 Metric)", Digikey Part Number=478-KGM15AR71A102KTCT-ND, Manufacturer="KYOCERA AVX", Mouser Part Number=581-0603ZC102K, Operating Temperature Range="-55°C to +125°C", TempCo=15%, Temperature Characteristic=X7R, Tolerance_%=10%, ValueDisplayed=1nF
C86 C124 C127: library part CMP-0096605-1, "100 pF ±5% 100V Ceramic Capacitor X7R 0603 (1608 Metric)", Digikey Part Number=478-12671-1-ND, Manufacturer="KYOCERA AVX", Mouser Part Number=581-06031C101JAT2A, Operating Temperature Range="-55°C to +125°C", TempCo=15%, Temperature Characteristic=X7R, Tolerance_%=5%, ValueDisplayed=100pF
C88 C119: library part CMP-0121624-1, "10 µF ±10% 16V Ceramic Capacitor X7R 0805 (2012 Metric)", Digikey Part Number=2997-MA0805XR106K160TR-ND, Manufacturer=Meritek, Operating Temperature Range="-55°C to +125°C", TempCo=15%, Temperature Characteristic=X7R, Tolerance_%=10%, ValueDisplayed=10uF
C89 C118: library part CMP-0095621-1, "22μF ±20% 10V Ceramic Capacitor X7T 0805 (2012 Metric)", Manufacturer=Murata, Mouser Part Number=81-GRT21BD71A226ME3L, Operating Temperature Range="-55°C to +125°C", TempCo=+22/-33%, Temperature Characteristic=X7T, Tolerance_%=20%, ValueDisplayed=22uF
C90 C91 C120 C121: library part CMP-0086419-2, "Cap Ceramic 0.015uF 50V X7R 10% Pad SMD 0603 125°C T/R", Manufacturer=Kemet, TempCo=15%, Tolerance_%=10%
C115: library part CMP-0006915-5, "CAP, CERM, 0.27 uF, 10 V, +/- 10%, X7R, 0603", Cap_Case=0603, Manufacturer=Kemet, Supplier Part Number 1=399-4914-1-ND, TempCo=X7R, Tolerance_%=10%, Value1=Unknown, Value2=10V, ValueDisplayed=0.27uF
C122: library part CMP-0081462-1, "CAP, AL, 100 µF, 25 V, +/- 20%, SMD", Cap_Case=6.3x7.7mm, Manufacturer=Nichicon, Supplier Part Number 1=493-2190-1-ND, Tolerance_%=20%, Value2=25V, ValueDisplayed=100µF
C134 C136 C139: library part CMP-0006970-4, "CAP, CERM, 82 pF, 50 V, +/- 10%, C0G/NP0, 0603", Cap_Case=0603, Manufacturer=Kemet, Supplier Part Number 1=399-1059-1-ND, TempCo=C0G/NP0, Tolerance_%=10%, Value1=Unknown, Value2=50V, ValueDisplayed=82pF
C158: library part CMP-0121052-1, "Cap Ceramic 1uF 25V X7R ±10% Pad SMD 0603 +125°C T/R", Digikey Part Number=1276-CL10B105KA8VPJCCT-ND, Manufacturer=Samsung, Mouser Part Number=187-CL10B105KA8VPJC, Operating Temperature Range="-55°C to +125°C", TempCo=15%, Temperature Characteristic=X7R, Tolerance_%=10%, ValueDisplayed=1uF
C159: library part CMP-0006753-4, "CAP, CERM, 0.1 uF, 25 V, +/- 10%, X7R, 0603", Cap_Case=0603, Manufacturer=AVX, Supplier Part Number 1=478-3714-1-ND, TempCo=X7R, Tolerance_%=10%, Value1="0.05 ohm", Value2=25V, ValueDisplayed=0.1uF
C160 C162: library part CMP-0860987-1, "CAP, CERM, 3900 pF, 100 V,+/- 5%, C0G/NP0, 0603", Cap_Case=0603, Manufacturer=TDK, TempCo=C0G/NP0, Tolerance_%=5%, Value2=100V, ValueDisplayed=3900pF
C172: library part CMP-0006853-4, "CAP, CERM, 0.01 uF, 16 V, +/- 10%, X7R, 0603", Cap_Case=0603, Manufacturer=Kemet, Supplier Part Number 1=399-7841-1-ND, TempCo=X7R, Tolerance_%=10%, Value1=Unknown, Value2=16V, ValueDisplayed=0.01uF
D3 D4 D7 D8 D11 D12 D15 D16 D19 D20 D23 D24: library part CMP-0077081-2, "Diode, Ultrafast, 1200 V, 1 A, SMA", Manufacturer=STMicroelectronics, Value1=1A, Value2=1.9V
D25: library part CMP-0092845-1, "LED Uni-Color Red 643nm 2-Pin Chip 0603(1608Metric) T/R", Color=Red, Digikey Part Number=475-3124-1-ND, Forward Current=2mA, Manufacturer="OSRAM Opto Semiconductors", Mouser Part Number=720-LSL29K-G1H2-1-Z, Operating Temperature Range="-40°C to +100°C"
D26 D27 D29 D31 D32: library part CMP-0002894-2, "LED, Green, SMD", Color=green, Manufacturer="Wurth Elektronik", Value1=W, Value2=2V
D30: library part CMP-0028350-2, "Diode, Schottky, 30 V, 3 A, SMA", Manufacturer="Diodes Inc.", Value1=3A, Value2=0.5V
D33: library part CMP-0028951-2, "Diode, Schottky, 60 V, 0.5 A, SOD-123", Manufacturer="Diodes Inc.", Value1=0.5A, Value2=0.5V
FID1 FID2 FID3: library part CMP-0077181-1, "Fiducial mark.  There is nothing to buy or mount.", Manufacturer=N/A
H1 H2 H3 H4 H5 H6 H7 H8 H9 H10 H11 H12 H13 H14 H16: library part CMP-0003617-1, "Machine Screw, Round, #4-40 x 1/4, Nylon, Philips panhead", Manufacturer="B&F Fastener Supply", Supplier Part Number 1=H542-ND
J3 J4 J9 J10 J24 J25 J26 J27: library part CMP-0082272-1, "Receptacle, 2.54mm, 3x2, Gold, SMT", Color=Black, Current_A=4.1A, Manufacturer=Samtec, Supplier Part Number 1=SAM9484-ND, Voltage_V=400V
J5 J6 J11 J12: library part CMP-0054757-1, "Power Element Bush, M4, 12, TH", Manufacturer="Wurth Elektronik", Supplier Part Number 1=732-3207-ND
J15 J16: library part CMP-0127514-1, "Conn Socket Strip SKT 10 POS 2.54mm Solder ST Top Entry SMD Tube", Current_A=4.1A, Digikey Part Number=SAM12618-ND, Manufacturer=Samtec, Mouser Part Number=200-HLE10502GDVBEA, Operating Temperature Range="-55°C to +125°C", Voltage_V=566V
J17: library part CMP-0003814-2, "C2000 controlCARD-120HSEC connector, SMT", Manufacturer=Samtec
J18: library part CMP-0003859-2, "C2000 controlCARD-180HSEC (60-pin addon) connector, SMT", Manufacturer=Samtec
J19: library part CMP-0054804-1, "Header, 2.54mm, 10x1, Gold, TH", Color=Black, Manufacturer="Wurth Elektronik", Supplier Part Number 1=732-2670-ND
J20 J22 J23: library part CMP-0075491-1, "Header, 100mil, 2x1, Tin, SMD", Color=Black, Current_A=5.4A, Manufacturer=Samtec, Supplier Part Number 1=77P4673, Voltage_V=475V
J21: library part CMP-0075012-1, "Power Jack, SMT", Manufacturer="CUI Inc.", Supplier Part Number 1=CP-002AHPJDKR-ND
J28 J29: library part CMP-0122568-1, "Mini-Latch™ Wire-to-Board Header, Vertical, with Friction Ramp, 3 Circuits, Gold (Au) Plating", Current_A=3A, Digikey Part Number=23-0022111031-ND, Manufacturer=Molex, Mouser Part Number=538-22-11-1031, Operating Temperature Range="-40°C to +105°C", Voltage_V=250V
L1 L2 L3: library part CMP-0062508-2, "Inductor, Shielded, Ferrite, 47 uH, 0.06 A, 1.7 ohm, SMD", Manufacturer=TDK, Supplier Part Number 1=445-1910-1-ND, Value1="1.7 ohm", Value2=0.06A, ValueDisplayed=47uH
L7: library part CMP-0128921-1, "4.7 µH Shielded Molded Inductor 5.3 A 36.96mOhm Max Nonstandard", Digikey Part Number=732-74439324047CT-ND, Manufacturer=Wurth, Mouser Part Number=710-74439324047, Operating Temperature Range="-40°C to +125°C", Self Resonant Frequency=28MHz, Test Frequency=100kHz, Tolerance_%=20%
LBL1: library part CMP-0003625-1, "Thermal Transfer Printable Labels, 0.650\" W x 0.200\" H - 10,000 per roll", Manufacturer=Brady, Supplier Part Number 1=97C5133
Logo1: library part CMP-0074844-1
Logo3: library part CMP-0074847-1, "FCC_disclaimer"
Logo4: library part CMP-0074769-1
LOGO6 LOGO8: library part CMP-0074837-2, "IEC 61010-1 Hot Surface Warning", Manufacturer="Texas Instruments"
LOGO7 LOGO9: library part CMP-0074835-1, "IEC 61010-1 High Voltage Warning"
MD2: library part CMP-0128745-2, "3300V 22.5mΩ Full-Bridge / Dual-Half-Bridge SiC Module", Drain To Source Breakdown Voltage=3300V, Input Capacitance At Vds="13820pF @ 2000V", Manufacturer="Navitas Semiconductor", Operating Temperature Range="-55°C to +175°C", Typ Forward Diode Voltage=4V
Q1: library part CMP-0000585-1, "MOSFET, N-CH, 30 V, 22 A, DQK0006C (WSON-6)", Alternate Manufacturer=None, Manufacturer="Texas Instruments", Supplier Part Number 1=296-37193-1-ND, Value1=0.02, Value2="2.4 nC"
Q2: library part CMP-0089138-1, "MOSFET N-CH 30V 5.8A SOT23", Digikey Part Number=DMN3042L-13DI-ND, Drain To Source Breakdown Voltage=30V, Input Capacitace At Vds="570pF @ 15V", Manufacturer=Diodes, Mouser Part Number=621-DMN3042L-13, Operating Temperature Range="-55°C to +150°C", Power_W=0.72W, Pulse Drain Current=30A, Typ Forward Diode Voltage=0.7V
R3 R4 R7 R8 R11 R12 R15 R16 R22 R24 R28 R32 R34 R36 R38 R40: library part CMP-0017868-2, "RES, 120 k, 1%, 0.25 W, 1206", Manufacturer="Yageo America", Power_W=250mW, Supplier Part Number 1=311-120KFRCT-ND, TempCo="100 ppm/C", Tolerance_%=1%, Value2=0.25W, Value_Code=120k
R19 R20 R29 R30 R45 R46 R47 R53 R54 R55 R120 R121 R122 R123 R149 R150 R205: library part CMP-0022684-3, "RES, 10.0 k, 1%, 0.1 W, 0603", Manufacturer=Panasonic, Power_W=100mW, Supplier Part Number 1=P10.0KHCT-ND, TempCo="100 ppm/C", Tolerance_%=1%, Value2=0.1W, Value_Code=10k0, ValueDisplayed=10.0k
R41 R43: library part CMP-0065757-2, "RES, 0.0005, 1%, 3 W, 4026", Manufacturer=Vishay-Dale, Power_W=3W, Supplier Part Number 1=WSLR-.0005CT-ND, TempCo="75 ppm/C", Tolerance_%=1%, Value_Code=L5000, ValueDisplayed=0.0005
R44 R56 R57 R68 R77 R78 R85 R86 R94 R109 R111 R112 R114 R115 R117 R118 R186 R189: library part CMP-0025880-3, "RES, 47, 5%, 0.1 W, AEC-Q200 Grade 0, 0603", Manufacturer=Panasonic, Power_W=100mW, Supplier Part Number 1=P47GCT-ND, TempCo="200 ppm/C", Tolerance_%=5%, Value2=0.1W, Value_Code=47R0, ValueDisplayed=47
R48 R49 R50 R147 R148: library part CMP-0082532-1, "RES, 499, 1%, 0.1 W, 0603", Manufacturer=Vishay-Dale, Power_W=100mW, Supplier Part Number 1=541-3986-1-ND, TempCo="100 ppm/C", Tolerance_%=1%, Value2=0.1W, Value_Code=499R, ValueDisplayed=499
R59 R61 R63 R66 R69 R70 R71 R72 R73 R74 R82 R83 R87 R88 R90 R100 R102 R104 R105 R106 R107 R108 R116 R119 R125 R126 R127 R128 R129 R130 R131 R132 R133 R215 R216 R217 R218: library part CMP-0097467-1, "0 Ohms Jumper 0.125W, 1/8W Chip Resistor 0603 (1608 Metric) Automotive AEC-Q200 Thick Film", Digikey Part Number=10-ERJ-H3G0R00VCT-ND, Manufacturer=Panasonic, Mouser Part Number=667-ERJ-H3G0R00V, Operating Temperature Range="-55°C to +175°C", Power_W=125mW
R134: library part CMP-0023128-4, "RES, 470 k, 1%, 0.1 W, 0603", Manufacturer=Yageo, Power_W=100mW, Supplier Part Number 1=311-470KHRCT-ND, TempCo="100 ppm/C", Tolerance_%=1%, Value2=0.1W, Value_Code=470k
R135 R139 R141 R143: library part CMP-0023133-5, "RES, 47.0 k, 1%, 0.1 W, 0603", Manufacturer=Yageo, Power_W=100mW, Supplier Part Number 1=311-47.0KHRCT-ND, TempCo="100 ppm/C", Tolerance_%=1%, Value2=0.1W, Value_Code=47k0, ValueDisplayed=47.0k
R136: library part CMP-0022870-5, "RES, 1.10 k, 1%, 0.1 W, 0603", Manufacturer=Yageo, Power_W=100mW, Supplier Part Number 1=311-1.10KHRCT-ND, TempCo="100 ppm/C", Tolerance_%=1%, Value2=0.1W, Value_Code=1k10, ValueDisplayed=1.10k
R137: library part CMP-0023203-5, "RES, 5.60 k, 1%, 0.1 W, 0603", Manufacturer=Yageo, Power_W=100mW, Supplier Part Number 1=311-5.60KHRCT-ND, TempCo="100 ppm/C", Tolerance_%=1%, Value2=0.1W, Value_Code=5k60, ValueDisplayed=5.60k
R138: library part CMP-0022763-5, "RES, 11.0 k, 1%, 0.1 W, 0603", Manufacturer=Yageo, Power_W=100mW, Supplier Part Number 1=311-11.0KHRCT-ND, TempCo="100 ppm/C", Tolerance_%=1%, Value2=0.1W, Value_Code=11k0, ValueDisplayed=11.0k
R140: library part CMP-0023000-5, "RES, 2.00 k, 1%, 0.1 W, 0603", Manufacturer=Yageo, Power_W=100mW, Supplier Part Number 1=311-2.00KHRCT-ND, TempCo="100 ppm/C", Tolerance_%=1%, Value2=0.1W, Value_Code=2k00, ValueDisplayed=2.00k
R142: library part CMP-0022816-5, "RES, 15.0 k, 1%, 0.1 W, 0603", Manufacturer=Yageo, Power_W=100mW, Supplier Part Number 1=311-15.0KHRCT-ND, TempCo="100 ppm/C", Tolerance_%=1%, Value2=0.1W, Value_Code=15k0, ValueDisplayed=15.0k
R144: library part CMP-0022917-4, "RES, 220 k, 1%, 0.1 W, 0603", Manufacturer=Yageo, Power_W=100mW, Supplier Part Number 1=311-220KHRCT-ND, TempCo="100 ppm/C", Tolerance_%=1%, Value2=0.1W, Value_Code=220k
R145: library part CMP-0023404-3, "RES, 10.0 k, 0.1%, 0.1 W, 0603", Manufacturer="Susumu Co Ltd", Power_W=100mW, Supplier Part Number 1=RG16P10.0KBCT-ND, TempCo="25 ppm/C", Tolerance_%=0.1%, Value2=0.1W, Value_Code=10k0, ValueDisplayed=10.0k
R146: library part CMP-0023020-5, "RES, 30.0 k, 1%, 0.1 W, 0603", Manufacturer=Yageo, Power_W=100mW, Supplier Part Number 1=311-30.0KHRCT-ND, TempCo="100 ppm/C", Tolerance_%=1%, Value2=0.1W, Value_Code=30k0, ValueDisplayed=30.0k
R151 R152 R181 R182: library part CMP-0025687-2, "RES, 10.0, 0.1%, 0.1 W, 0603", Manufacturer=Vishay-Dale, Power_W=100mW, Supplier Part Number 1=TNP10.0AACT-ND, TempCo="25 ppm/C", Tolerance_%=0.1%, Value2=0.1W, Value_Code=10R0, ValueDisplayed=10.0
R153 R163 R183: library part CMP-0023099-5, "RES, 40.2, 1%, 0.1 W, 0603", Manufacturer=Yageo, Power_W=100mW, Supplier Part Number 1=311-40.2HRCT-ND, TempCo="100 ppm/C", Tolerance_%=1%, Value2=0.1W, Value_Code=40R2, ValueDisplayed=40.2
R154: library part CMP-0022736-4, "RES, 100, 1%, 0.1 W, 0603", Manufacturer=Yageo, Power_W=100mW, Supplier Part Number 1=311-100HRCT-ND, TempCo="100 ppm/C", Tolerance_%=1%, Value2=0.1W, Value_Code=100R, ValueDisplayed=100
R158 R159 R160 R161 R162: library part CMP-0120473-1, "Thick Film High Voltage Chip Resistors 1206 1.5MOhm ±1% ±100ppm/°C", Manufacturer=Bourns, Operating Temperature Range="-55°C to +155°C", Power_W=250mW, TempCo=100ppm/°C, Tolerance_%=1%
R164: library part CMP-0023153-5, "RES, 4.70 k, 1%, 0.1 W, 0603", Manufacturer=Yageo, Power_W=100mW, Supplier Part Number 1=311-4.70KHRCT-ND, TempCo="100 ppm/C", Tolerance_%=1%, Value2=0.1W, Value_Code=4k70, ValueDisplayed=4.70k
R165 R185: library part CMP-0025892-5, "RES, 18 k, 5%, 0.1 W, 0603", Manufacturer=Yageo, Power_W=100mW, Supplier Part Number 1=311-18KGRCT-ND, TempCo="100 ppm/C", Tolerance_%=5%, Value2=0.1W, Value_Code=18k0, ValueDisplayed=18k
R184: library part CMP-0022680-4, "RES, 1.00 k, 1%, 0.1 W, 0603", Manufacturer=Panasonic, Power_W=100mW, Supplier Part Number 1=P1.00KHCT-ND, TempCo="100 ppm/C", Tolerance_%=1%, Value2=0.1W, Value_Code=1k00, ValueDisplayed=1.00k
R187: library part CMP-0023921-2, "RES, 200, 0.1%, 0.1 W, 0603", Manufacturer="Yageo America", Power_W=100mW, TempCo="25 ppm/C", Tolerance_%=0.1%, Value2=0.1W, Value_Code=200R, ValueDisplayed=200
R188: library part CMP-0098286-1, "10 kOhms ±5% 0.1W, 1/10W Chip Resistor 0603 (1608 Metric) Thick Film", Digikey Part Number=541-CRCW060310K0JNEBCCT-ND, Manufacturer=Vishay, Mouser Part Number=71-CRCW060310K0JNEBC, Operating Temperature Range="-55°C to +155°C", Power_W=100mW, TempCo=200ppm/°C, Tolerance_%=5%
R190: library part CMP-0023235-5, "RES, 680, 1%, 0.1 W, 0603", Manufacturer=Yageo, Power_W=100mW, Supplier Part Number 1=311-680HRCT-ND, TempCo="100 ppm/C", Tolerance_%=1%, Value2=0.1W, Value_Code=680R, ValueDisplayed=680
R193 R196 R208: library part CMP-0023069-5, "RES, 390, 1%, 0.1 W, 0603", Manufacturer=Yageo, Power_W=100mW, Supplier Part Number 1=311-390HRCT-ND, TempCo="100 ppm/C", Tolerance_%=1%, Value2=0.1W, Value_Code=390R, ValueDisplayed=390
R194 R197 R209: library part CMP-0022769-5, "RES, 120, 1%, 0.1 W, 0603", Manufacturer=Yageo, Power_W=100mW, Supplier Part Number 1=311-120HRCT-ND, TempCo="100 ppm/C", Tolerance_%=1%, Value2=0.1W, Value_Code=120R, ValueDisplayed=120
R195 R198 R210: library part CMP-0025815-4, "RES, 47, 5%, 0.1 W, AEC-Q200 Grade 0, 0603", Manufacturer=Vishay-Dale, Power_W=100mW, Supplier Part Number 1=541-47GCT-ND, TempCo="200 ppm/C", Tolerance_%=5%, Value2=0.1W, Value_Code=47R0, ValueDisplayed=47
R199: library part CMP-0022553-4, "RES, 68.1, 1%, 0.1 W, AEC-Q200 Grade 0, 0603", Manufacturer=Vishay-Dale, Power_W=100mW, Supplier Part Number 1=541-68.1HCT-ND, TempCo="100 ppm/C", Tolerance_%=1%, Value2=0.1W, Value_Code=68R1, ValueDisplayed=68.1
R200 R201 R206 R207 R211 R212 R213 R214: library part CMP-0018693-3, "RES, 4.7, 5%, 0.25 W, AEC-Q200 Grade 0, 1206", Manufacturer=Vishay-Dale, Power_W=250mW, Supplier Part Number 1=541-4.7ECT-ND, TempCo="200 ppm/C", Tolerance_%=5%, Value2=0.25W, Value_Code=4R70, ValueDisplayed=4.7
R202: library part CMP-0025942-5, "RES, 8.2 k, 5%, 0.1 W, 0603", Manufacturer=Yageo, Power_W=100mW, Supplier Part Number 1=311-8.2KGRCT-ND, TempCo="100 ppm/C", Tolerance_%=5%, Value2=0.1W, Value_Code=8k20, ValueDisplayed=8.2k
R203: library part CMP-0025894-5, "RES, 1.2 k, 5%, 0.1 W, 0603", Manufacturer=Yageo, Power_W=100mW, Supplier Part Number 1=311-1.2KGRCT-ND, TempCo="100 ppm/C", Tolerance_%=5%, Value2=0.1W, Value_Code=1k20, ValueDisplayed=1.2k
TP1 TP3 TP14: library part CMP-0055147-2, "Test Point, Multipurpose, Red, TH", Color=Red, Manufacturer="Keystone Electronics", Supplier Part Number 1=36-5010-ND
TP2 TP18 TP21 TP22 TP23: library part CMP-0055148-2, "Test Point, Multipurpose, Black, TH", Color=Black, Manufacturer="Keystone Electronics", Supplier Part Number 1=36-5011-ND
TP4 TP5 TP6 TP7 TP8 TP9 TP10 TP11 TP12 TP13 TP15 TP16 TP20: library part CMP-0055155-2, "Test Point, Compact, Blue, TH", Color=Blue, Manufacturer="Keystone Electronics", Supplier Part Number 1=36-5122-ND
U2: library part CMP-0093039-1, "Schmitt-trigger inputs quadruple bus buffer gates with 3-state outputs 14-SOIC -40 to 125", Manufacturer="Texas Instruments", Max Supply Voltage=6V, Min Supply Voltage=2V, Mouser Part Number=595-SN74HCS126DR, Nominal Supply Current=0.1uA, Operating Temperature Range="-40°C to +125°C"
U3: library part CMP-0088329-1, "2.7- 23V, 5.5 A, 28 mΩ Reverse Current Blocking eFuse with Input Reverse Polarity Protection", Manufacturer="Texas Instruments", Max Supply Voltage=23V, Min Supply Voltage=2.7V, Nominal Supply Current=0.5-6A, Operating Temperature Range="-40°C to +125°C", Output Voltage=42V, Threshold Voltage=1.2/1.1V
U4: library part CMP-0074640-3, "500-mA, Low IQ, Small Size, Low Dropout Regulator, DBV0005A (SOT-23-5)", Alternate Manufacturer="Texas Instruments"
U5: library part CMP-0047826-1, "4.2-V to 17-V Input, 3-A Synchronous Buck Converter in SOT563", Manufacturer="Texas Instruments", Max Supply Voltage=17V, Min Supply Voltage=4.2V, Nominal Supply Current=110uA, Operating Temperature Range="-40°C to +125°C", Output Voltage=0.6-7V, Switching Frequency=600kHz
U6: library part CMP-0125127-1, "Automotive, Precision, ±250-mV Input Isolated Delta-Sigma Modulators With External Clock", Manufacturer="Texas Instruments", Max Supply Voltage=5.5V, Min Supply Voltage=2.7V, Operating Temperature Range="-40°C to +125°C"
U7: library part CMP-0860008-1, "AMC1336 Small, High-Precision, Reinforced Isolated Delta-Sigma Modulator With Input Optimized for Voltage Sensing Applications, DWV0008A (SOIC-8)", Alternate Manufacturer="Texas Instruments", Alternate PartNumber=AMC1336DWV
U8 U13: library part CMP-0123146-1, "Ultra-Small, 1.5W, 5.0V, 5kVRMS Isolation, Industrial DC/DC Module", Manufacturer="Texas Instruments", Max Supply Voltage=5.5V, Min Supply Voltage=4.5V, Nominal Supply Current=7-545mA, Operating Temperature Range="-40°C to +125°C", Output Voltage=5/5.5V, Switching Frequency=76MHz
U12: library part CMP-0092444-3, "Dual, Fast Response, Reinforced Isolated Window Comparator with Adjustable Threshold", Manufacturer="Texas Instruments", Operating Temperature Range=to
U14 U15: library part CMP-0122473-1, "Automotive ±1.5°C, 3-kVRMS Isolated Temperature Sensor With Analog Output With < 2 Seconds Response Time and 500VRMS Working Voltage", Manufacturer="Texas Instruments", Max Supply Voltage=5.5V, Min Supply Voltage=2.3V, Operating Supply Current=10uA, Operating Temperature Range="-40°C to +150°C"
U16: library part CMP-0081550-1, "Low-Power, Rail-to-Rail In and Out, 1-MHz Operational Amplifier, DBV0005A (SOT-23-5)", Alternate Manufacturer="Texas Instruments", Alternate PartNumber=TLV9001IDBVT
U19 U21 U23: library part CMP-0092228-1, "Fiber Optic Transmitter 650nm 1.8V TOSLINK", Digikey Part Number=TOTX1350(F)-ND, Forward Current=6mA, Manufacturer=Toshiba, Max Supply Voltage=5.25V, Min Supply Voltage=4.75V, Mouser Part Number=757-TOTX1350F, Operating Temperature Range="-40°C to +85°C"
U20 U22 U24: library part CMP-0092227-1, "Fiber Optic Receiver General Purpose 10Mbps -27dBm 4.75V ~ 5.25V", Digikey Part Number=TORX1350A(F)-ND, Manufacturer=Toshiba, Max Supply Voltage=5.25V, Min Supply Voltage=4.75V, Mouser Part Number=757-TORX1350AF, Operating Temperature Range="-40°C to +85°C"
U25: library part CMP-0097984-1, Manufacturer="Texas Instruments", Operating Temperature Range=to
U26 U27 U28: library part CMP-0093827-1, "Single-Bit Fixed Direction Voltage-Level Translator with Schmitt-Trigger Inputs and 3-State Outputs", Manufacturer="Texas Instruments", Operating Temperature Range="-40°C to +125°C"
U29: library part CMP-0051712-2, "Single Power Supply BUFFER Logic Level Shifter (no enable), DBV0005A, LARGE T&R", Alternate Manufacturer="Texas Instruments", F @ Nom Voltage(Max)(Mhz)=50, Generic Part Number=SN74LV1T34, ICC @ Nom Voltage(Max)(mA)=0.01, Operating Temperature Range(C)="-40 to 125", Rating=Catalog, tpd @ Nom Voltage(Max)(ns)=14.5,9.5,8.0,6.5, Voltage(Nom)(V)=1.8,2.5,3.3,5.5
ZZ1: library part CMP-0003616-3
ZZ2: library part CMP-0077236-1
ZZ3: library part CMP-0077237-1
ZZ4: library part CMP-0077238-1

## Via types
v1: diameter 0.6, hole 0.2, Top Layer to Bottom Layer, tented both sides, 1862 vias
v2: diameter 0.61, hole 0.203, Top Layer to Bottom Layer, tented both sides, 6 vias

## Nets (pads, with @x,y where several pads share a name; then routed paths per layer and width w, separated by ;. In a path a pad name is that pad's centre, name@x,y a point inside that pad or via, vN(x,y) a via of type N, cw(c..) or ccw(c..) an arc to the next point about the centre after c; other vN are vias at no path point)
3V3: C66.1 C73.1 C74.1 C82.1 C83.1 C113.1 C114.1 C123.1 C126.1 C129.1 C141.2 C143.2 C145.2 C158.2 C159.1 D32.2 J19.10 R45.2 R46.2 R47.2 R104.1 R149.2 R150.2 R202.1 R218.2 TP3.1 U4.5 U6.8 U7.8 U12.8 U14.1 U15.1 U16.5 U25.9 U25.10 U26.3 U26.6 U27.3 U27.6 U28.3 U28.6 | length 579.1
  Top Layer w0.25: 28.963,126.862 44.862,126.862 46,128 v1(46,129) ; v1(29,128) 29,126.898 28.077,125.975 18.9,125.975 15,122.075 15,58 7,50 7,47 9,45 25,45 v1(29,41) 42,41 TP3.1@53,30 ; v1(54.043,17.957) 59,13 83.007,13 84.007,14 v1(86.009,14) 89.02,14 ; v1(89,28) 89.02,27.98 89.02,14 ; v1(146,42) v1(150,46) 150.988,46 ; v1(151,48) 151,46.012 150.988,46 ; v1(158,15) 157.246,15.754 ; v1(160,3) v1(160,11) ; v1(168,23) 160.036,23 160,23.036 ; v1(177,27) 177,30 175,32 166,32 ; 89.02,14 101,14 102,13 v1(112.979,13) 154.493,13 157.246,15.754 ; 150.988,46 153,46 155,48 v1(166,48) 166,32 ; 157.246,15.754 160,18.507 160,23.036 ; 160,23.036 160,26 166,32
  Bottom Layer w0.25: U14.1@19.905,24.3 19.905,23.15 20.051,23.004 20.118,23.004 20.66,22.462 C123.1@20.66,22.357 21.357,22.357 25.145,26.145 25.145,31.145 29,35 v1(29,41) ; v1(29,128) 29,128.854 C74.1@29.32,129.175 29.461,129.315 U6.8@29.461,133.863 ; U7.8@45.996,134.013 46.025,133.984 46.025,131.914 C82.1@46.054,131.885 46.054,130.261 C83.1@46,130.206 ; v1(46,129) 46,130.198 C83.1@46.008,130.206 ; 49,29 49,23 v1(54.043,17.957) 56.957,17.957 62.277,23.277 R45.2@64.066,23.277 67.97,23.277 R47.2@68,23.307 ; D32.2@50.85,32.05 D32.2@51,32.2 ; J19.10@82.749,2.976 86.009,6.236 v1(86.009,14) ; R104.1@87.725,28 v1(89,28) ; v1(112.979,13) 112.979,7.244 116.014,4.208 R150.2@116.014,4.183 R149.2@118.027,4.183 ; R218.2@122.725,43 127.474,43 127.795,42.679 127.795,42.102 U16.5@127.896,42.002 ; U16.5@127.97,41.927 127.97,42.076 129.216,42.076 129.895,42.755 134.755,42.755 138,46 v1(150,46) ; v1(146,42) 140,42 139,41 139,36 139.755,35.245 C126.1@145.267,35.245 145.342,35.17 147.225,35.17 U15.1@147.3,35.095 ; v1(151,48) 151.723,48 153.182,49.459 C114.1@153.207,49.459 ; C114.1@153.21,49.459 153.56,49.809 U12.8@153.56,53.5 ; v1(158,15) 160,13 v1(160,11) ; v1(160,3) 160,3.095 160.28,3.374 160.28,3.744 160.536,4 C145.2@160.599,4 ; C145.2@160.663,4 160.919,4.256 160.919,4.619 160.975,4.675 160.975,5.425 U28.3@161,5.45 U28.6@161,8.55 ; v1(166,48) 166,52 172,58 172,60 ; v1(168,23) 169.238,23 169.75,23.512 U27.3@169.75,24.45 U27.6@169.75,27.55 ; U25.9@173.325,67.247 U25.10@172.055,67.247 172.055,64.062 171.755,63.762 C158.2@171.755,62 172,61.755 172,60 ; R202.1@174.2,60 172,60 ; v1(177,27) C141.2@179.175,27 ; C141.2@179.238,27 179.494,27.256 179.494,27.319 179.5,27.325 U26.3@179.5,29 U26.6@179.5,32.1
